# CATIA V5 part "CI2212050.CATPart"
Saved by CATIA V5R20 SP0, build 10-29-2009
Part number: CI2212050
Bounding box of the stored display mesh (mm): x -12 to 12, y -16.675 to 13.021, z -68 to 9.46
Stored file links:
  C:\Users\Raffaele\Desktop\3D X SITO CF\BOLEX\19-INCLINED ASSEMBLY REF_CI\CI2212050.CATPart
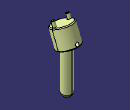
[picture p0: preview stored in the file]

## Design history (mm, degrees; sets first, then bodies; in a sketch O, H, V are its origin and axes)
Set1
  DatumSurface1 to DatumSurface16 "MANIFOLD_SOLID_BREP #377"
  DatumSurface17 to DatumSurface39 "MANIFOLD_SOLID_BREP #1127"
Body1 (main body)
